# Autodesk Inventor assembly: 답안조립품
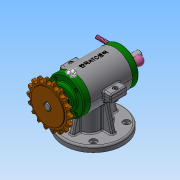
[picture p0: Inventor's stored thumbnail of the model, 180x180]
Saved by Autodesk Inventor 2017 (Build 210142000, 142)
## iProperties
Part Number: 답안조립품
Material: 일반
Document SubType Name: Assembly
Designer: user
Author: user
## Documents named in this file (19)
- C:\Users\user\Desktop\611206V1003\답안조립품.iam
- C:\Users\user\Desktop\611206V1003\본체.ipt
- C:\Users\user\Desktop\611206V1003\상부커버.ipt
- C:\Users\user\Desktop\611206V1003\볼트 M4 x 16.ipt
- C:\Users\user\Desktop\611206V1003\앞커버.ipt
- C:\Users\user\Desktop\611206V1003\뒤커버.ipt
- C:\Users\user\Desktop\611206V1003\베어링 6201.ipt
- C:\Users\user\Desktop\611206V1003\베어링 6202.ipt
- C:\Users\user\Desktop\611206V1003\편심축.ipt
- C:\Users\user\Desktop\611206V1003\오일실 12 x 22 x 7.ipt
- C:\Users\user\Desktop\611206V1003\키 4 x 4.ipt
- C:\Users\user\Desktop\611206V1003\볼트 M3 x 0.5.ipt
- C:\Users\user\Desktop\611206V1003\스프로킷.ipt
- C:\Users\user\Desktop\611206V1003\멈춤나사 M3.ipt
- C:\Users\user\Desktop\611206V1003\레버.ipt
- C:\Users\user\Desktop\611206V1003\와셔.ipt
- C:\Users\user\Desktop\611206V1003\너트 M4.ipt
- C:\Users\user\Desktop\611206V1003\슬라이드.ipt
- C:\Users\user\Desktop\611206V1003\가변스프링.ipt
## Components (7 placed, 4 different names)
1. ISO 4762 M4 x 16:1
2. ISO 4762 M4 x 16:2
3. ISO 7091 ST 4 - 100 HV:1
4. ISO 7091 ST 4 - 100 HV:2
5. ISO 4032 M4:1
6. ISO 4032 M4:2
7. 가변스프링:1
